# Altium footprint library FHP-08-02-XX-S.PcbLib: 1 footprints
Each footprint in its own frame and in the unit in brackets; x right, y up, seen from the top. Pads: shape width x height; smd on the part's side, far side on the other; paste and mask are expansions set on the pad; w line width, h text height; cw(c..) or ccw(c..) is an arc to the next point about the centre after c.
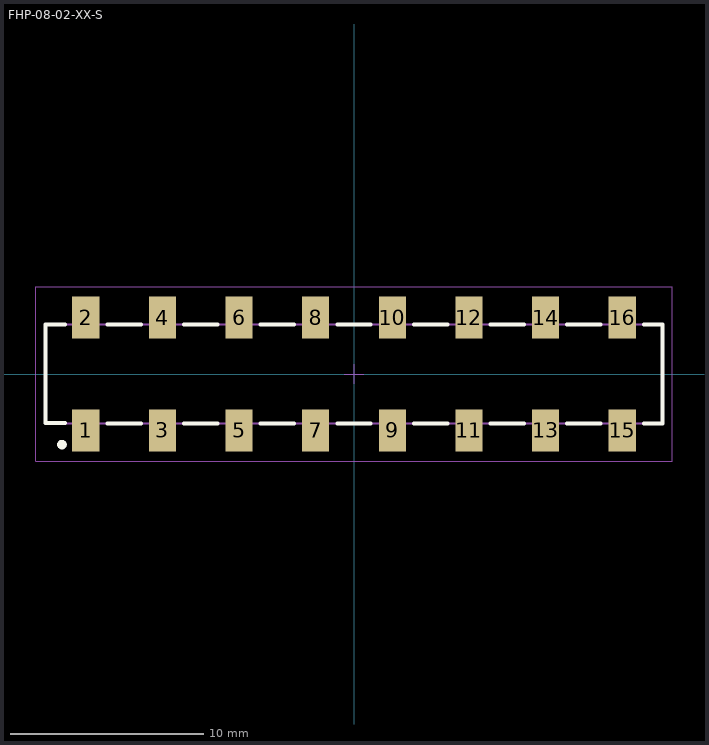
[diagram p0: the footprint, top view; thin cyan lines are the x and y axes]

## FHP-08-02-XX-S [mm] "3.96mm pitch, 8 pin, power socket strip"
height 9.35
pads (16):
  rect 1.4x2.15 smd mask+0: 1(-13.868,-2.921) 2(-13.868,2.921) 3(-9.906,-2.921) 4(-9.906,2.921) 5(-5.944,-2.921) 6(-5.944,2.921) 7(-1.981,-2.921) 8(-1.981,2.921) 9(1.981,-2.921) 10(1.981,2.921) 11(5.944,-2.921) 12(5.944,2.921) 13(9.906,-2.921) 14(9.906,2.921) 15(13.868,-2.921) 16(13.868,2.921)
Top Overlay:
  circle w0.25: c-15.1,-3.65 r0.125
  lines w0.2: -14.95,-2.54 -15.95,-2.54 -15.95,2.55 -14.95,2.55 ; -12.75,-2.55 -11,-2.55 ; -12.75,2.55 -11,2.55 ; -8.8,-2.55 -7.05,-2.55 ; -8.8,2.55 -7.05,2.55 ; -4.85,-2.55 -3.1,-2.55 ; -4.85,2.55 -3.1,2.55 ; -0.85,-2.55 0.85,-2.55 ; -0.85,2.55 0.85,2.55 ; 3.1,-2.55 4.85,-2.55 ; 3.1,2.55 4.85,2.55 ; 7.05,-2.55 8.8,-2.55 ; 7.05,2.55 8.8,2.55 ; 11,-2.55 12.75,-2.55 ; 11,2.55 12.75,2.55 ; 15,-2.55 15.95,-2.55 15.95,2.55 15,2.55
Mechanical 12:
  lines w0.001: -15.95,-2.55 15.95,-2.55 15.95,2.55 -15.95,2.55 -15.95,-2.55
Mechanical 13:
  lines w0.1: -15.95,-2.55 15.95,-2.55 15.95,2.55 -15.95,2.55 -15.95,-2.55
  text ".Designator" at 0.508,1.016 h1.52
Mechanical 15:
  lines w0.05: -0.5,0 0.5,0 ; 0,-0.5 0,0.5 ; -16.45,-4.5 16.45,-4.5 16.45,4.5 -16.45,4.5 -16.45,-4.5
